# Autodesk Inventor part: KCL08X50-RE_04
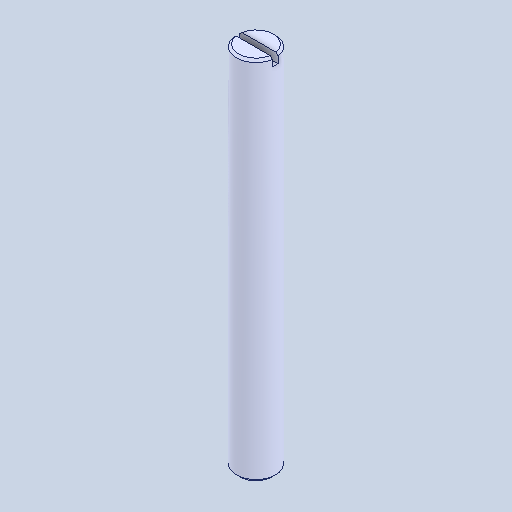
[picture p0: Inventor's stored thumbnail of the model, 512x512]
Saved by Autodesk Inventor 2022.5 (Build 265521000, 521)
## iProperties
Created: 2024-08
Part Number: KCL08X50-RE_04
Material: 一般
Document SubType Name: Modeling
Designer: ImaoCorp
Density: 1 g/cm^3
Appearance: 既定
Author: ImaoCorp
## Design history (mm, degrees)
feature "KCL08X50-RE_04"
node "ソリッド1"
